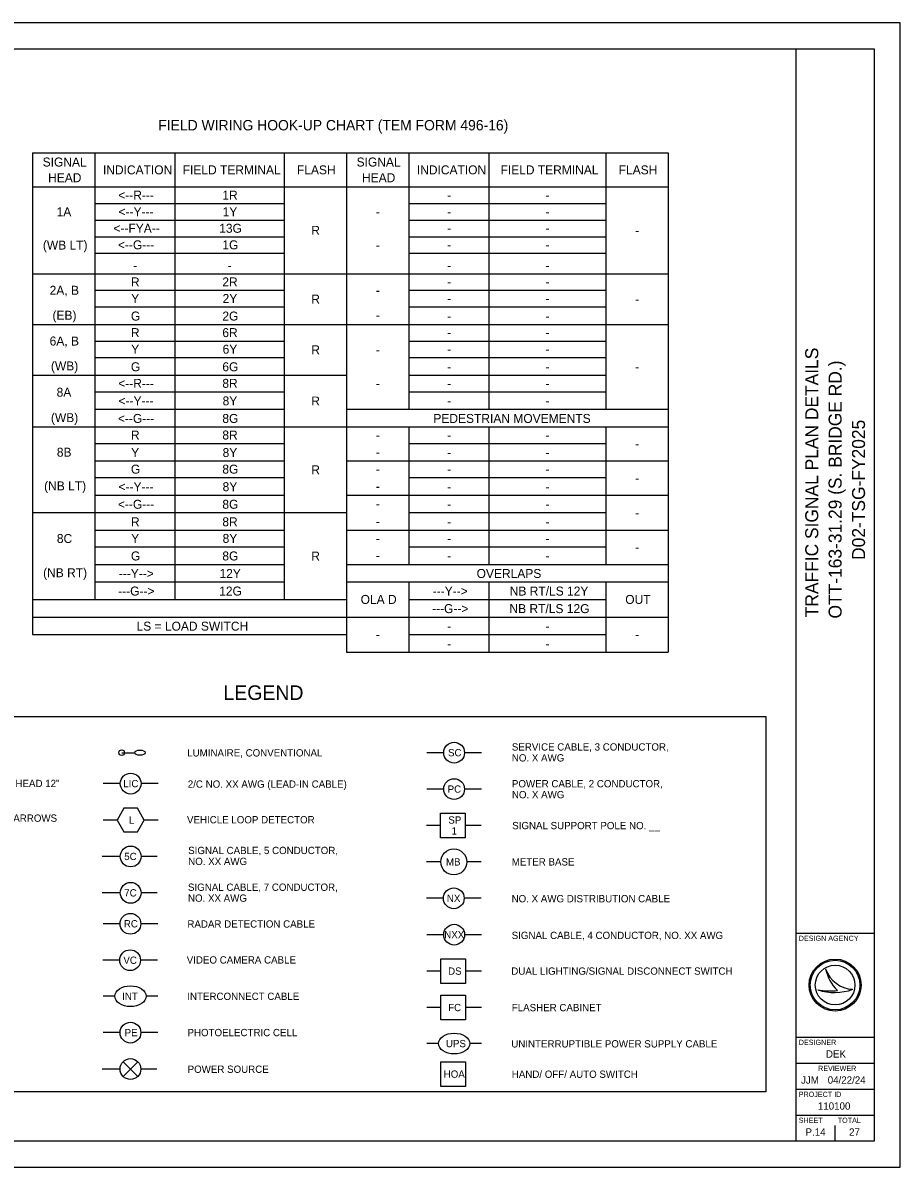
# Model space of a CAD drawing. Extents: x 0 to 680, y 0 to 440.
# Drawn here: x 342.6 to 680, y 0 to 440 of the extents above; entities that cross this region are included whole.
import ezdxf

# ---------------------------------------------------------------- set-up
doc = ezdxf.new("R2010")
doc.units = 0
for name, color, linetype in [('Default', 7, 'Continuous'), ('LT_P_Luminaires', 7, 'Continuous'), ('SG_P_Text', 7, 'Continuous'), ('SH_Border', 7, 'Continuous'), ('SH_Cut_Line', 7, 'Continuous'), ('SH_Data', 7, 'Continuous'), ('SH_Text', 7, 'Continuous')]:
    doc.layers.add(name, color=color, linetype=linetype)

msp = doc.modelspace()

# ---------------------------------------------------------------- linework, layer by layer
at = {"layer": 'Default'}
for p, q in [((346.31, 390.04), (590.81, 390.04)), ((346.31, 390.04), (346.31, 204.79)), ((370.31, 390.04), (370.31, 218.29)), ((401.06, 390.04), (401.06, 218.29)), ((443.06, 390.04), (443.06, 218.29)), ((467.06, 390.04), (467.06, 198.04)), ((491.06, 390.04), (491.06, 291.42)), ((521.81, 390.04), (521.81, 291.42)), ((566.81, 390.04), (566.81, 291.42)), ((590.81, 390.04), (590.81, 198.04)), ((346.31, 376.92), (590.81, 376.92)), ((370.31, 370.54), (443.06, 370.54)), ((491.06, 370.54), (566.81, 370.54)), ((370.31, 364.17), (443.06, 364.17)), ((491.06, 364.17), (566.81, 364.17)), ((370.31, 357.79), (443.06, 357.79)), ((491.06, 357.79), (566.81, 357.79)), ((370.31, 351.42), (443.06, 351.42)), ((491.06, 351.42), (566.81, 351.42)), ((346.31, 343.54), (590.81, 343.54)), ((370.31, 337.17), (443.06, 337.17)), ((491.06, 337.17), (566.81, 337.17)), ((370.31, 330.79), (443.06, 330.79)), ((491.06, 330.79), (566.81, 330.79)), ((346.31, 324.04), (590.81, 324.04)), ((370.31, 317.67), (443.06, 317.67)), ((491.06, 317.67), (566.81, 317.67)), ((370.31, 311.29), (443.06, 311.29)), ((491.06, 311.29), (566.81, 311.29)), ((346.31, 304.54), (467.06, 304.54)), ((491.06, 304.54), (566.81, 304.54)), ((370.31, 298.17), (443.06, 298.17)), ((491.06, 298.17), (566.81, 298.17)), ((370.31, 291.42), (443.06, 291.42)), ((467.06, 291.42), (590.81, 291.42)), ((346.31, 284.67), (590.81, 284.67)), ((491.06, 284.67), (491.06, 231.79)), ((521.81, 284.67), (521.81, 231.79)), ((566.81, 284.67), (566.81, 231.79)), ((370.31, 278.29), (443.06, 278.29)), ((491.06, 278.29), (566.81, 278.29)), ((370.31, 271.54), (443.06, 271.54)), ((467.06, 271.54), (590.81, 271.54)), ((370.31, 265.17), (443.06, 265.17)), ((491.06, 265.17), (566.81, 265.17)), ((370.31, 258.42), (443.06, 258.42)), ((467.06, 258.42), (590.81, 258.42)), ((346.31, 251.67), (467.06, 251.67)), ((491.06, 251.67), (566.81, 251.67)), ((370.31, 244.92), (443.06, 244.92)), ((467.06, 244.92), (590.81, 244.92)), ((370.31, 238.54), (443.06, 238.54)), ((491.06, 238.54), (566.81, 238.54)), ((370.31, 231.79), (443.06, 231.79)), ((467.06, 231.79), (590.81, 231.79)), ((370.31, 225.04), (443.06, 225.04)), ((467.06, 225.04), (590.81, 225.04)), ((491.06, 225.04), (491.06, 198.04)), ((521.81, 225.04), (521.81, 198.04)), ((566.81, 225.04), (566.81, 198.04)), ((346.31, 218.29), (467.06, 218.29)), ((491.06, 218.29), (566.81, 218.29)), ((346.31, 211.54), (521.81, 211.54)), ((521.81, 211.54), (566.81, 211.54)), ((566.81, 211.54), (590.81, 211.54)), ((346.31, 204.79), (467.06, 204.79)), ((491.06, 204.79), (566.81, 204.79)), ((467.06, 198.04), (590.81, 198.04))]:
    msp.add_line(p, q, dxfattribs=at)
at = {"layer": 'LT_P_Luminaires'}
msp.add_line((380.58, 159.37), (385.58, 159.37), dxfattribs=at)
msp.add_circle((380.58, 159.37), 1.1, dxfattribs=at)
msp.add_ellipse((387.58, 159.37), major_axis=(2, 0), ratio=0.5, dxfattribs=at)
at = {"layer": 'SG_P_Text'}
for p, q in [((504.45, 159.37), (497.91, 159.37)), ((518.99, 159.37), (512.45, 159.37)), ((380.04, 147.47), (373.5, 147.47)), ((394.58, 147.47), (388.04, 147.47)), ((504.45, 145.37), (497.91, 145.37)), ((518.99, 145.37), (512.45, 145.37)), ((378.85, 133.47), (373.5, 133.47)), ((394.58, 133.47), (389.24, 133.47)), ((503.25, 131.37), (497.78, 131.37)), ((518.86, 131.37), (512.73, 131.37)), ((380.04, 119.47), (373.13, 119.47)), ((394.21, 119.47), (388.04, 119.47)), ((503.32, 117.37), (497.78, 117.37)), ((518.86, 117.37), (513.32, 117.37)), ((380.04, 105.47), (373.13, 105.47)), ((394.21, 105.47), (388.04, 105.47)), ((504.32, 103.37), (497.78, 103.37)), ((518.86, 103.37), (512.32, 103.37)), ((379.95, 93.57), (373.41, 93.57)), ((394.49, 93.57), (387.95, 93.57)), ((504.46, 89.37), (497.92, 89.37)), ((519.01, 89.37), (512.46, 89.37)), ((379.82, 79.57), (373.28, 79.57)), ((394.36, 79.57), (387.82, 79.57)), ((503.4, 75.37), (497.92, 75.37)), ((519.01, 75.37), (512.87, 75.37)), ((377.95, 65.71), (373.41, 65.71)), ((394.49, 65.71), (389.95, 65.71)), ((503.4, 61.37), (497.92, 61.37)), ((519.01, 61.37), (512.87, 61.37)), ((379.95, 51.71), (373.41, 51.71)), ((394.49, 51.71), (387.95, 51.71)), ((502.46, 47.51), (497.92, 47.51)), ((519.01, 47.51), (514.46, 47.51)), ((381.12, 40.54), (386.78, 34.88)), ((381.12, 34.88), (386.78, 40.54)), ((379.95, 37.71), (373.04, 37.71)), ((394.12, 37.71), (387.95, 37.71))]:
    msp.add_line(p, q, dxfattribs=at)
for points in [[(389.24, 133.47), (386.64, 137.97), (381.44, 137.97), (378.85, 133.47), (381.44, 128.97), (386.64, 128.97)], [(503.25, 136.11), (512.73, 136.11), (512.73, 126.64), (503.25, 126.64)], [(503.4, 80.11), (512.87, 80.11), (512.87, 70.64), (503.4, 70.64)], [(503.4, 66.11), (512.87, 66.11), (512.87, 56.64), (503.4, 56.64)], [(503.4, 40.5), (512.87, 40.5), (512.87, 31.03), (503.4, 31.03)]]:
    msp.add_lwpolyline(points, close=True, dxfattribs=at)
for centre, radius in [((508.45, 159.37), 4), ((384.04, 147.47), 4), ((508.45, 145.37), 4), ((384.04, 119.47), 4), ((508.32, 117.37), 5), ((384.04, 105.47), 4), ((508.32, 103.37), 4), ((383.95, 93.57), 4), ((508.46, 89.37), 4), ((383.82, 79.57), 4), ((383.95, 51.71), 4), ((383.95, 37.71), 4)]:
    msp.add_circle(centre, radius, dxfattribs=at)
for centre in [(383.95, 65.71), (508.46, 47.51)]:
    msp.add_ellipse(centre, major_axis=(6, 0), ratio=0.666667, dxfattribs=at)
at = {"layer": 'SH_Border'}
for p, q in [((640, 10), (640, 430)), ((640, 90), (670, 90)), ((640, 50), (670, 50)), ((640, 40), (670, 40)), ((640, 30), (670, 30)), ((640, 20), (670, 20))]:
    msp.add_line(p, q, dxfattribs=at)
msp.add_lwpolyline([(30, 430), (670, 430), (670, 10), (30, 10)], close=True, dxfattribs=at)
at = {"layer": 'SH_Cut_Line'}
msp.add_lwpolyline([(0, 0), (680, 0), (680, 440), (0, 440)], close=True, dxfattribs=at)
at = {"layer": 'SH_Data'}
for p, q in [((651.35, 76.19), (651.35, 76.19)), ((648.34, 68.19), (648.34, 68.19)), ((655, 70), (655, 70)), ((661.75, 68.37), (661.75, 68.37)), ((647.5, 13.5), (647.5, 13.5)), ((655, 10), (655, 16))]:
    msp.add_line(p, q, dxfattribs=at)
for radius in [10, 9.54, 9.54, 7.64]:
    msp.add_circle((655, 70), radius, dxfattribs=at)
for centre, radius, start, end in [((662.32, 79.95), 11.6, 198.9257, 198.9319), ((666.93, 79.4), 15.91, 191.6379, 191.6421), ((662.32, 79.95), 11.6, 198.9319, 267.1657), ((666.93, 79.4), 15.91, 191.6421, 226.0947), ((654.79, 87.4), 20.26, 251.4576, 290.0832), ((652.96, 93.09), 25.32, 259.4964, 259.4995), ((654.79, 87.4), 20.26, 251.4527, 251.4576), ((652.96, 93.09), 25.32, 259.4995, 276.6672)]:
    msp.add_arc(centre, radius, start, end, dxfattribs=at)
at = {"layer": 'SH_Text'}
msp.add_lwpolyline([(231.79, 173.25), (628.35, 173.25), (628.35, 29), (231.79, 29)], close=True, dxfattribs=at)

# ---------------------------------------------------------------- texts
at = {"layer": 'Default'}
for s, p in [('SIGNAL ', (350.18, 384.77)), ('SIGNAL ', (470.93, 384.77)), ('INDICATION', (373.37, 381.75)), ('FIELD TERMINAL', (404.05, 381.75)), ('FLASH', (448, 381.75)), ('INDICATION', (494.12, 381.75)), ('FIELD TERMINAL', (526.3, 381.75)), ('FLASH', (571.75, 381.75)), ('HEAD', (352.27, 378.73)), ('HEAD', (473.02, 378.73)), ('<--R---', (379.26, 372.04)), ('1R', (419.3, 372.04)), ('-', (505.73, 372.04)), ('-', (543.6, 372.04)), ('1A', (355.55, 365.63)), ('<--Y---', (379.38, 365.67)), ('1Y', (419.4, 365.67)), ('-', (478.35, 365.63)), ('-', (505.73, 365.67)), ('-', (543.6, 365.67)), ('<--FYA--', (377.41, 359.29)), ('13G', (418.09, 359.29)), ('R', (453.5, 358.5)), ('-', (505.73, 359.29)), ('-', (543.6, 359.29)), ('(WB LT)', (350.27, 352.84)), ('<--G---', (379.14, 352.92)), ('1G', (419.3, 352.92)), ('-', (578.1, 358.5)), ('-', (478.35, 352.84)), ('-', (505.73, 352.92)), ('-', (543.6, 352.92)), ('-', (384.98, 345.04)), ('-', (421.35, 345.04)), ('-', (505.73, 345.04)), ('-', (543.6, 345.04)), ('2A, B', (352.87, 335.44)), ('R', (384.13, 338.67)), ('2R', (419.3, 338.67)), ('-', (505.73, 338.67)), ('-', (543.6, 338.67)), ('Y', (384.23, 332.29)), ('2Y', (419.4, 332.29)), ('R', (453.5, 332.07)), ('-', (478.35, 335.44)), ('-', (505.73, 332.29)), ('-', (543.6, 332.29)), ('-', (578.1, 332.07)), ('(EB)', (353.96, 325.84)), ('G', (384.13, 325.54)), ('2G', (419.3, 325.54)), ('-', (478.35, 325.84)), ('-', (505.73, 325.54)), ('-', (543.6, 325.54)), ('R', (384.13, 319.17)), ('6R', (419.3, 319.17)), ('6A, B', (352.87, 315.94)), ('-', (505.73, 319.17)), ('-', (543.6, 319.17)), ('Y', (384.23, 312.79)), ('6Y', (419.4, 312.79)), ('R', (453.5, 312.57)), ('-', (478.35, 312.57)), ('-', (505.73, 312.79)), ('-', (543.6, 312.79)), ('(WB)', (353.36, 306.34)), ('G', (384.13, 306.04)), ('6G', (419.3, 306.04)), ('-', (505.73, 306.04)), ('-', (543.6, 306.04)), ('-', (578.1, 306)), ('8A', (355.55, 296.25)), ('<--R---', (379.26, 299.67)), ('8R', (419.3, 299.67)), ('-', (478.35, 299.59)), ('-', (505.73, 299.67)), ('-', (543.6, 299.67)), ('<--Y---', (379.38, 292.92)), ('8Y', (419.4, 292.92)), ('R', (453.5, 292.88)), ('-', (505.73, 292.92)), ('-', (543.6, 292.92)), ('(WB)', (353.36, 286.47)), ('<--G---', (379.14, 286.17)), ('8G', (419.3, 286.17)), ('PEDESTRIAN MOVEMENTS', (500.47, 286.17)), ('R', (384.13, 279.79)), ('8R', (419.3, 279.79)), ('-', (478.35, 279.75)), ('-', (505.73, 279.79)), ('-', (543.6, 279.79)), ('-', (578.1, 276.38)), ('8B', (355.64, 273.19)), ('Y', (384.23, 273.04)), ('8Y', (419.4, 273.04)), ('-', (478.35, 273.19)), ('-', (505.73, 273.04)), ('-', (543.6, 273.04)), ('G', (384.13, 266.67)), ('8G', (419.3, 266.67)), ('R', (453.5, 266.44)), ('-', (478.35, 266.63)), ('-', (505.73, 266.67)), ('-', (543.6, 266.67)), ('-', (578.1, 263.25)), ('(NB LT)', (350.75, 260.22)), ('<--Y---', (379.38, 259.92)), ('8Y', (419.4, 259.92)), ('-', (478.35, 260.07)), ('-', (505.73, 259.92)), ('-', (543.6, 259.92)), ('<--G---', (379.14, 253.17)), ('8G', (419.3, 253.17)), ('-', (478.35, 253.32)), ('-', (505.73, 253.17)), ('-', (543.6, 253.17)), ('-', (578.1, 249.94)), ('R', (384.13, 246.42)), ('8R', (419.3, 246.42)), ('-', (478.35, 246.57)), ('-', (505.73, 246.42)), ('-', (543.6, 246.42)), ('8C', (355.65, 240)), ('Y', (384.23, 240.04)), ('8Y', (419.4, 240.04)), ('-', (478.35, 240)), ('-', (505.73, 240.04)), ('-', (543.6, 240.04)), ('-', (578.1, 236.63)), ('G', (384.13, 233.29)), ('8G', (419.3, 233.29)), ('R', (453.5, 233.25)), ('-', (478.35, 233.44)), ('-', (505.73, 233.29)), ('-', (543.6, 233.29)), ('(NB RT)', (350.35, 226.84)), ('---Y-->', (379.46, 226.54)), ('12Y', (418.2, 226.54)), ('OVERLAPS', (517.11, 226.54)), ('---G-->', (379.22, 219.79)), ('12G', (418.09, 219.79)), ('OLA D', (472.5, 216.57)), ('---Y-->', (500.21, 219.79)), ('NB RT/LS 12Y', (529.84, 219.79)), ('OUT', (574.28, 216.57)), ('---G-->', (499.97, 213.04)), ('NB RT/LS 12G', (529.74, 213.04)), ('LS = LOAD SWITCH', (386.3, 206.29)), ('-', (505.73, 206.29)), ('-', (543.6, 206.29)), ('-', (478.35, 203.07)), ('-', (578.1, 203.07)), ('-', (505.73, 199.54)), ('-', (543.6, 199.54))]:
    msp.add_text(s, height=3.45, dxfattribs=at).set_placement(p)
at = {"layer": 'SG_P_Text'}
for s, p in [('SC', (506.09, 157.97)), ('LIC', (381.19, 146.07)), ('PC', (505.95, 143.97)), ('L', (383.35, 132.07)), ('SP', (506.22, 132.07)), ('1', (507.45, 127.87)), ('5C', (381.56, 118.07)), ('MB', (505.3, 115.97)), ('7C', (381.56, 104.07)), ('NX', (505.65, 101.97)), ('RC', (381.41, 92.17)), ('NXX', (504.65, 87.97)), ('VC', (381.22, 78.17)), ('DS', (506.12, 73.97)), ('INT', (380.75, 64.31)), ('FC', (506.15, 59.97)), ('PE', (381.7, 50.31)), ('UPS', (505.29, 46.11)), ('HOA', (504.44, 34.37))]:
    msp.add_text(s, height=2.8, dxfattribs=at).set_placement(p)
at = {"layer": 'SH_Data'}
for s, p in [('TRAFFIC SIGNAL PLAN DETAILS', (648.5, 211.45)), ('OTT-163-31.29 (S. BRIDGE RD.)', (657.5, 210.96)), ('D02-TSG-FY2025', (666.5, 233.5))]:
    msp.add_text(s, height=5, rotation=90, dxfattribs=at).set_placement(p)
for s, height, p in [('DESIGN AGENCY', 2, (641, 87)), ('DESIGNER', 2, (641, 47)), ('DEK', 2.8, (651.47, 42.1)), ('REVIEWER', 2, (648.44, 37)), ('JJM', 2.8, (641.89, 32.1)), ('04/22/24', 2.8, (652.16, 32.1)), ('PROJECT ID', 2, (641, 27)), ('110100', 2.8, (648.37, 22.1)), ('SHEET', 2, (641, 17)), ('TOTAL', 2, (656, 17)), ('P.14', 2.8, (643.63, 12.1)), ('27', 2.8, (660.37, 12.1))]:
    msp.add_text(s, height=height, dxfattribs=at).set_placement(p)
at = {"layer": 'SH_Text'}
for s, height, p in [('FIELD WIRING HOOK-UP CHART (TEM FORM 496-16)', 4, (394.66, 398.66)), ('LEGEND', 5.6, (419.71, 179.65)), ('SERVICE CABLE, 3 CONDUCTOR,', 2.8, (530.65, 160.18)), ('LUMINAIRE, CONVENTIONAL', 2.8, (405.78, 157.9)), ('NO. X AWG', 2.8, (530.65, 155.98)), ('TRAFFIC SIGNAL, 2 UNIT, 3 UNIT, OR PHB HEAD 12"', 2.8, (263.78, 146.14)), ('2/C NO. XX AWG (LEAD-IN CABLE)', 2.8, (406.01, 145.89)), ('POWER CABLE, 2 CONDUCTOR,', 2.8, (530.68, 146.03)), ('NO. X AWG', 2.8, (530.68, 141.83)), ('TRAFFIC SIGNAL, 3 UNIT HEAD, 12" WITH ARROWS', 2.8, (263.7, 132.8)), ('VEHICLE LOOP DETECTOR', 2.8, (405.7, 132.19)), ('SIGNAL SUPPORT POLE NO. __', 2.8, (530.79, 129.94)), ('SIGNAL CABLE, 5 CONDUCTOR, ', 2.8, (406.16, 120.37)), ('NO. XX AWG', 2.8, (406.16, 116.17)), ('METER BASE', 2.8, (530.6, 115.98)), ('SIGNAL CABLE, 7 CONDUCTOR, ', 2.8, (406.08, 106.24)), ('NO. XX AWG', 2.8, (406.08, 102.04)), ('NO. X AWG DISTRIBUTION CABLE', 2.8, (530.56, 101.83)), ('RADAR DETECTION CABLE', 2.8, (405.85, 92.09)), ('SIGNAL CABLE, 4 CONDUCTOR, NO. XX AWG', 2.8, (530.59, 87.71)), ('VIDEO CAMERA CABLE', 2.8, (405.59, 78.28)), ('DUAL LIGHTING/SIGNAL DISCONNECT SWITCH', 2.8, (530.44, 73.98)), ('INTERCONNECT CABLE', 2.8, (405.82, 64.28)), ('FLASHER CABINET', 2.8, (530.63, 59.94)), ('PHOTOELECTRIC CELL', 2.8, (405.89, 50.35)), ('UNINTERRUPTIBLE POWER SUPPLY CABLE', 2.8, (530.43, 46.01)), ('POWER SOURCE', 2.8, (405.94, 36.25)), ('HAND/ OFF/ AUTO SWITCH', 2.8, (530.63, 34.33))]:
    msp.add_text(s, height=height, dxfattribs=at).set_placement(p)

doc.saveas('drawing.dxf')
